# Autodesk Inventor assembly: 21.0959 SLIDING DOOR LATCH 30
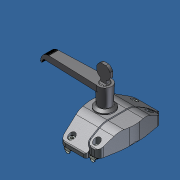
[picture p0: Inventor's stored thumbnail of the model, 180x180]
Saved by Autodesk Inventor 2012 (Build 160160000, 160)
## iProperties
Created: 2014-06
Part Number: 21.0959 SLIDING DOOR LATCH 30
Document SubType Name: Assembly
Designer: Admin
Mass: 450 g
Surface Area: 556.881 cm^2
Volume: 140.222 cm^3
Author: Admin
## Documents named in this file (4)
- C:\Andys Backup Data\ANDY'S INVENTOR\INVENTOR LIBRARIES\PARTS LIBRARY\30 SERIES\21.0959 SLIDING DOOR LATCH 30.iam
- C:\Andys Backup Data\ANDY'S INVENTOR\INVENTOR LIBRARIES\PARTS LIBRARY\30 SERIES\SUBCOMPONENTS\21.0959 SLIDING DOOR LATCH 30 HANDLE SIDE.ipt
- C:\Andys Backup Data\ANDY'S INVENTOR\INVENTOR LIBRARIES\PARTS LIBRARY\30 SERIES\SUBCOMPONENTS\21.0959 SLIDING DOOR LATCH 30 CATCH SIDE.ipt
- C:\Andys Backup Data\ANDY'S INVENTOR\INVENTOR LIBRARIES\PARTS LIBRARY\HANDLES LOCKS STOPS\SUBCOMPONENTS\21.1758 SNAP BOLT 25.ipt
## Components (3 placed, 3 different names)
1. 21.0959 SLIDING DOOR LATCH 30 HANDLE SIDE:1 — Flush:2, Flush:3, Mate:2
2. 21.0959 SLIDING DOOR LATCH 30 CATCH SIDE:1 — Mate:1, Flush:1, Angle:1, Flush:2, Flush:3, Mate:2
3. 21.1758 SNAP BOLT 25:1 — Mate:1, Flush:1, Angle:1
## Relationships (6: Flush 3, Mate 2, Angle 1)
- Mate:1: 21.0959 SLIDING DOOR LATCH 30 CATCH SIDE:1 ↔ 21.1758 SNAP BOLT 25:1
- Flush:1: 21.0959 SLIDING DOOR LATCH 30 CATCH SIDE:1 ↔ 21.1758 SNAP BOLT 25:1
- Angle:1: 21.0959 SLIDING DOOR LATCH 30 CATCH SIDE:1 ↔ 21.1758 SNAP BOLT 25:1
- Flush:2: 21.0959 SLIDING DOOR LATCH 30 HANDLE SIDE:1 ↔ 21.0959 SLIDING DOOR LATCH 30 CATCH SIDE:1
- Flush:3: 21.0959 SLIDING DOOR LATCH 30 HANDLE SIDE:1 ↔ 21.0959 SLIDING DOOR LATCH 30 CATCH SIDE:1
- Mate:2: 21.0959 SLIDING DOOR LATCH 30 HANDLE SIDE:1 ↔ 21.0959 SLIDING DOOR LATCH 30 CATCH SIDE:1
